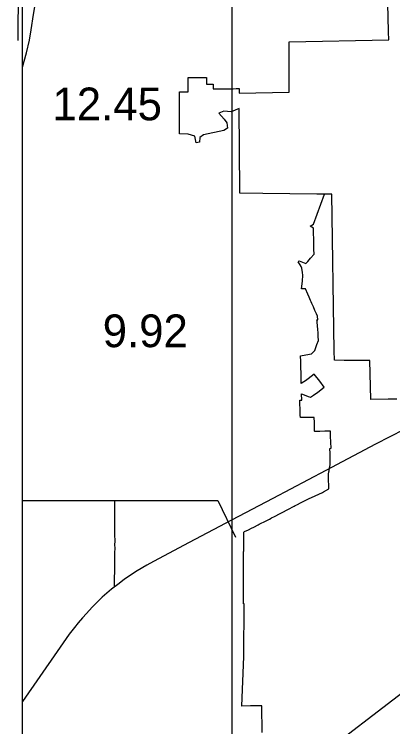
# Model space of a CAD drawing. Extents: x 1127717 to 1741049, y 2026793 to 2244711.
# Drawn here: x 1238385 to 1240828, y 2140586 to 2145187 of the extents above; entities that cross this region are included whole.
import ezdxf

# ---------------------------------------------------------------- set-up
doc = ezdxf.new("R2010")
doc.units = 0
for name, color, linetype in [('1', 7, 'Continuous'), ('10', 7, 'Continuous'), ('15', 7, 'Continuous'), ('30', 7, 'Continuous'), ('5', 7, 'Continuous'), ('58', 7, 'Continuous'), ('6', 7, 'Continuous')]:
    doc.layers.add(name, color=color, linetype=linetype)

msp = doc.modelspace()

# ---------------------------------------------------------------- linework, layer by layer
at = {"layer": '1'}
msp.add_lwpolyline([(1238438.2, 2155644.2), (1269451.6, 2155644.2), (1269451.6, 2123596.1), (1238438.2, 2123596.1)], close=True, dxfattribs=at)
at = {"layer": '10'}
for points in [[(1238438.2, 2144844.4), (1238463.7, 2144937), (1238483.5, 2145018.4), (1238493.6, 2145086.4), (1238509.5, 2145184.9), (1238534.2, 2145338.9), (1238553.6, 2145470.6), (1238564.8, 2145509.4), (1238592.6, 2145596.6), (1238631.8, 2145711.8), (1238674.3, 2145838), (1238705.9, 2145932.6)], [(1238438.2, 2142046.7), (1238545, 2142046), (1239698.5, 2142047.2), (1239812.8, 2141810.5)], [(1239032.1, 2141489.6), (1239034.6, 2141646.2), (1239034.7, 2141668), (1239034.8, 2141706.8), (1239035.3, 2141741.4), (1239034.7, 2141758.8), (1239035, 2141786.5), (1239034.6, 2141824.2), (1239034.8, 2141857.5), (1239034.7, 2141885.7), (1239034.6, 2141911.8), (1239034.5, 2141927.5), (1239033.1, 2142046.5)], [(1240958.6, 2140856.9), (1240283.3, 2140339.5)]]:
    msp.add_lwpolyline(points, dxfattribs=at)
at = {"layer": '15'}
msp.add_lwpolyline([(1240901.2, 2142506), (1240717.4, 2142410), (1240395.8, 2142240.2), (1240053.6, 2142060.6), (1239786.4, 2141920.4), (1239513.4, 2141776), (1239282.5, 2141652.2), (1239239.9, 2141629.6), (1239177.8, 2141592.2), (1239129, 2141559.8), (1239093.9, 2141536.4), (1239052.5, 2141505.3), (1239012.7, 2141474.7), (1238982.1, 2141449), (1238952.6, 2141422.4), (1238920.3, 2141391.1), (1238887.5, 2141358.3), (1238851, 2141317.3), (1238825, 2141289.8), (1238796.7, 2141256.6), (1238773.3, 2141226.6), (1238738.9, 2141182.7), (1238662.4, 2141071.5), (1238438.2, 2140748.8)], dxfattribs=at)
at = {"layer": '30'}
msp.add_line((1239791.2, 2119636.1), (1239791.2, 2151684.2), dxfattribs=at)
at = {"layer": '5'}
msp.add_lwpolyline([(1238384.5, 2147717.8), (1238396.2, 2146691), (1238409.8, 2145357.2), (1238408.6, 2145017.9)], dxfattribs=at)
at = {"layer": '6'}
for points in [[(1239717, 2144705.6), (1239733.5, 2144705.7), (1239750, 2144705.9), (1239765.8, 2144706), (1239782.1, 2144706.1), (1239798.7, 2144706.2), (1239817, 2144706.3), (1239836.5, 2144706.4), (1239836.3, 2144686.5), (1239836.6, 2144678.1), (1240159.3, 2144683.6), (1240159.3, 2144687), (1240159.3, 2144689.8), (1240159.3, 2144692.6), (1240159.2, 2144759.4), (1240159.2, 2144762.7), (1240159.2, 2144766), (1240159.2, 2144833.9), (1240159.2, 2144836.4), (1240159, 2145008.7), (1240802.5, 2145021.7), (1240801.1, 2145072.9), (1240801.1, 2145075.3), (1240801, 2145077.8), (1240796.3, 2145253.7)], [(1240159.2, 2144833.9), (1240159.2, 2144836.4), (1240159, 2145008.7), (1240802.5, 2145021.7), (1240801.1, 2145072.9), (1240801.1, 2145075.3), (1240801, 2145077.8), (1240796.3, 2145253.7)], [(1240854.4, 2142701.6), (1240804.3, 2142701), (1240799.4, 2142700.9), (1240687.5, 2142699.6), (1240679.7, 2142950.5), (1240514.9, 2142951.8), (1240452, 2142952.3), (1240451, 2143014), (1240434.9, 2144024.7), (1240394.7, 2144025.1), (1240388.5, 2144025.1), (1240384.3, 2144025.2), (1240382.4, 2144025.2), (1240381.4, 2144025.2), (1240378.4, 2144025.2), (1240337.7, 2144025.7), (1239989.7, 2144029.1), (1239841.8, 2144030.6), (1239841.7, 2144047.4), (1239837.4, 2144578), (1239785.5, 2144555.9), (1239737, 2144561.2), (1239704.9, 2144547.4), (1239739.6, 2144509.7), (1239756.5, 2144484.9), (1239761.5, 2144450.2), (1239736.6, 2144436), (1239606.8, 2144409.1), (1239581.8, 2144390.4), (1239579.8, 2144360.4), (1239559.1, 2144355.4), (1239549.9, 2144399.4), (1239506.6, 2144413), (1239451.2, 2144415.5), (1239450.9, 2144684.8), (1239506.5, 2144685.1), (1239506.4, 2144777.8), (1239519, 2144777.8), (1239548.3, 2144778), (1239566.3, 2144778.2), (1239583.5, 2144778.3), (1239601.6, 2144778.4), (1239619.8, 2144778.5), (1239626.1, 2144778.6), (1239626.1, 2144747.6), (1239626.1, 2144744.4), (1239626.1, 2144741.9), (1239626.1, 2144739.4), (1239626.1, 2144735), (1239667.7, 2144735.3), (1239667.8, 2144705.3), (1239684.1, 2144705.4), (1239700.8, 2144705.5), (1239717, 2144705.6), (1239733.5, 2144705.7), (1239750, 2144705.9), (1239765.8, 2144706), (1239782.1, 2144706.1), (1239798.7, 2144706.2), (1239817, 2144706.3), (1239836.5, 2144706.4), (1239836.3, 2144686.5), (1239836.6, 2144678.1), (1240159.3, 2144683.6), (1240159.3, 2144687), (1240159.3, 2144689.8), (1240159.3, 2144692.6), (1240159.2, 2144759.4), (1240159.2, 2144762.7), (1240159.2, 2144766), (1240159.2, 2144833.9)], [(1240388.5, 2144025.1), (1240384.3, 2144025.2), (1240382.4, 2144025.2), (1240381.4, 2144025.2), (1240378.4, 2144025.2), (1240337.7, 2144025.7), (1239989.7, 2144029.1), (1239841.8, 2144030.6), (1239841.7, 2144047.4), (1239837.4, 2144578), (1239785.5, 2144555.9), (1239737, 2144561.2), (1239704.9, 2144547.4), (1239739.6, 2144509.7), (1239756.5, 2144484.9), (1239761.5, 2144450.2), (1239736.6, 2144436), (1239606.8, 2144409.1), (1239581.8, 2144390.4), (1239579.8, 2144360.4), (1239559.1, 2144355.4), (1239549.9, 2144399.4), (1239506.6, 2144413), (1239451.2, 2144415.5), (1239450.9, 2144684.8), (1239506.5, 2144685.1), (1239506.4, 2144777.8), (1239519, 2144777.8), (1239548.3, 2144778), (1239566.3, 2144778.2), (1239583.5, 2144778.3), (1239601.6, 2144778.4), (1239619.8, 2144778.5), (1239626.1, 2144778.6), (1239626.1, 2144747.6), (1239626.1, 2144744.4), (1239626.1, 2144741.9), (1239626.1, 2144739.4), (1239626.1, 2144735), (1239667.7, 2144735.3), (1239667.8, 2144705.3), (1239684.1, 2144705.4), (1239700.8, 2144705.5), (1239717, 2144705.6)], [(1240224.7, 2143594.1), (1240266.7, 2143576.5), (1240279, 2143590.4), (1240297.2, 2143610.9), (1240319.9, 2143636.6), (1240319.3, 2143670.9), (1240318.8, 2143697.1), (1240318.3, 2143720.8), (1240317.9, 2143743.2), (1240317.5, 2143765.1), (1240317, 2143790.4), (1240316.8, 2143804.8), (1240295.1, 2143818), (1240315.9, 2143832.3), (1240388.5, 2144025.1)], [(1240374.4, 2142099.5), (1240380.9, 2142103), (1240415.5, 2142121.7), (1240415.4, 2142126.8), (1240414.7, 2142145.8), (1240413.7, 2142175.1), (1240413.2, 2142191), (1240412.5, 2142210.3), (1240413.1, 2142213.8), (1240413.7, 2142217.4), (1240415.9, 2142231.3), (1240417.1, 2142238.4), (1240418.4, 2142246.6), (1240419.2, 2142251.2), (1240420.3, 2142258), (1240421.3, 2142264), (1240423.9, 2142279.9), (1240424.4, 2142283.4), (1240425, 2142286.8), (1240423.5, 2142350), (1240422.7, 2142382.8), (1240422.6, 2142383.5), (1240429.6, 2142384.5), (1240426.5, 2142461.9), (1240425.2, 2142494.9), (1240389.9, 2142494.2), (1240356.4, 2142493.5), (1240350.9, 2142493.4), (1240345.8, 2142493.3), (1240327.1, 2142492.9), (1240324.1, 2142492.8), (1240324, 2142494.1), (1240323.6, 2142511.2), (1240322.7, 2142550.3), (1240321.8, 2142583.3), (1240299.7, 2142583), (1240298, 2142583), (1240261, 2142582.6), (1240233.2, 2142582.2), (1240231.7, 2142582.2), (1240231.5, 2142588.1), (1240231.4, 2142591.7), (1240230.8, 2142612.5), (1240228.3, 2142693.8), (1240240.8, 2142694), (1240239.6, 2142735.2), (1240256.3, 2142728.9), (1240282.5, 2142719.1), (1240298.1, 2142713.2), (1240316.9, 2142727.2), (1240343.7, 2142747), (1240386.2, 2142778.6), (1240356.4, 2142817.6), (1240321.4, 2142863.2), (1240281.9, 2142833), (1240265.2, 2142820.3), (1240254.9, 2142813.4), (1240254.4, 2142813), (1240237.6, 2142801.8), (1240237.2, 2142818.1), (1240237, 2142828.6), (1240237, 2142829.8), (1240233.8, 2142944.3), (1240232.8, 2142980.7), (1240267.8, 2142987.8), (1240302.7, 2142994.8), (1240325.9, 2143014.9), (1240337.7, 2143053.3), (1240349.5, 2143080), (1240349.4, 2143080.5), (1240347.5, 2143107.4), (1240345.7, 2143129.7), (1240343.8, 2143152.1), (1240342, 2143174.5), (1240340.1, 2143198.3), (1240339.4, 2143205.3), (1240339.2, 2143208.2), (1240338.9, 2143211.1), (1240338.7, 2143213.4), (1240344.7, 2143213.3), (1240342.9, 2143236.3), (1240335.6, 2143252.8), (1240326, 2143274.8), (1240316.3, 2143296.8), (1240306.7, 2143318.8), (1240301.9, 2143329.6), (1240297.8, 2143339), (1240288.8, 2143359.6), (1240280.2, 2143379.1), (1240264.9, 2143414.1), (1240252.8, 2143414.3), (1240238.4, 2143414.5), (1240245.3, 2143463.5), (1240247.2, 2143501.8), (1240246.3, 2143520.1), (1240241.7, 2143546.2), (1240237.3, 2143558.2), (1240231.2, 2143568.5), (1240218.2, 2143587.9), (1240224.7, 2143594.1)], [(1239985, 2140548.6), (1239981.9, 2140720.9), (1239945.6, 2140720.6), (1239927.5, 2140720.4), (1239919.7, 2140720.4), (1239909.4, 2140720.4), (1239853.5, 2140718.7), (1239867.2, 2141039.8), (1239869.9, 2141379.6), (1239864.7, 2141379.5), (1239865.2, 2141549.1), (1239865.3, 2141600.9), (1239865.6, 2141711.6), (1239865.6, 2141712.4), (1239865.6, 2141714.1), (1239865.6, 2141714.3), (1239865.6, 2141714.6), (1239865.6, 2141716.6), (1239865.6, 2141717.5), (1239865.7, 2141718.9), (1239865.7, 2141721.5), (1239865.8, 2141740.9), (1239865.9, 2141772.9), (1239865.9, 2141781.2), (1239866, 2141788), (1239866, 2141795.7), (1239866, 2141801.4), (1239866.1, 2141809.2), (1239866.1, 2141815.8), (1239866.1, 2141821.7), (1239866.2, 2141827), (1239866.2, 2141832.3), (1239866.2, 2141835.4), (1239866.2, 2141843.3), (1239871.7, 2141845.9), (1239896.9, 2141858.1), (1239915.9, 2141867.3), (1239931.3, 2141874.7), (1239960.1, 2141889.7), (1239966.5, 2141893), (1240010.2, 2141915.7), (1240031.4, 2141926.8), (1240042.5, 2141932.5), (1240046, 2141934.3), (1240049.5, 2141936.2), (1240059.4, 2141941.3), (1240061, 2141942.1), (1240156.1, 2141991.5), (1240188.3, 2142008.2), (1240192.4, 2142010.4), (1240193.4, 2142010.9), (1240195.9, 2142012.2), (1240197.8, 2142013.2), (1240199.2, 2142013.9), (1240209.3, 2142019.2), (1240222.2, 2142025.9), (1240224.2, 2142026.9), (1240262.1, 2142046.7), (1240283.7, 2142058), (1240326.5, 2142077.6), (1240374.4, 2142099.5)]]:
    msp.add_lwpolyline(points, dxfattribs=at)

# ---------------------------------------------------------------- texts
at = {"layer": '58'}
for s, p in [('12.45', (1238631.2, 2144502.1)), ('9.92', (1238955.6, 2143037))]:
    msp.add_text(s, height=211.2, dxfattribs=at).set_placement(p)

doc.saveas('drawing.dxf')
